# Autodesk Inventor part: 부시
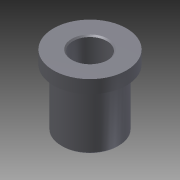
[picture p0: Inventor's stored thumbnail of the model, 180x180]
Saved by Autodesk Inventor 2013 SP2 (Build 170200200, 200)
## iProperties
Company: 한국ATC센터
Created: 2015-11
Part Number: 부시
Document SubType Name: Modeling
Designer: mdu
Density: 7.86 g/cm^3
Material: 강철, 연강
Mass: 67.5146 g
Surface Area: 43.3569 cm^2
Volume: 8.58964 cm^3
Author: mdu
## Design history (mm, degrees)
sketch "스케치1"
  geometry: C1 r 11 at (0, 0) reference; C2 r 14 at (0, 0) reference; C3 r 11 at (0, 0) reference; 1 further point
  node "참조1"
  node "참조2"
extrude "돌출1" new body sketch "스케치1" distance "d0" = 5; taper "d1" = 0 deg
extrude "돌출2" join sketch "스케치1" distance "d2" = 24; taper "d3" = 0 deg
hole "구멍1" diameter "d6" = 13; stored, may be unused: countersink angle "d10" = 90 deg, drill point angle "d12" = 118 deg; dims "d4" = 10, "d5" = 10, "d7" = 6, "d8" = 4, "d9" = 2, "d11" = 8
chamfer "모따기1" distance "d13" = 0.5; stored, may be unused: second distance "d14" = 2, angle "d15" = 45 deg
chamfer "모따기2" distance "d16" = 0.5; stored, may be unused: second distance "d17" = 2, angle "d18" = 45 deg
node "솔리드1"
